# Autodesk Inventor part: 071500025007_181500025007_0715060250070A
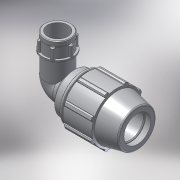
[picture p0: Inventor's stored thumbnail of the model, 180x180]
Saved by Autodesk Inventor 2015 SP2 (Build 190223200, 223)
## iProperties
Created: 2017-02
Part Number: 071500025007_181500025007_0715060250070A
Material: PVC-Piping
Description: PLASSON 90° ELBOW FEMALE ADAPTOR 25-3/4"
Document SubType Name: Modeling
Designer: KIM
Mass: 92.6774 g
Surface Area: 199.44 cm^2
Volume: 66.1981 cm^3
Density: 1.4 g/cm^3
Appearance: Smooth - White
Author: KIM
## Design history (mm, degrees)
derived "07150.ipt"
feature "Solid1::07150.ipt"
tag "TaggingFeature1"
body "Solid1"
other parameters: "d2" = 25, "d4" = 6.75, "d5" = 20.25, "d7" = 54, "d9" = 11.57143, "d11" = 2.7, "d13" = 120 deg, "d14" = 37.5, "d15" = 12 deg, "d16" = 46.98, "d18" = 1.25, "d19" = 35 deg, "d20" = 17.5 deg, "d21" = 50.22, "d23" = 0, "d25" = 360 deg, "d27" = 1.08, "d33" = 0.5, "d42" = 29.97, "d43" = 1.62, "d46" = 0.75, "d51" = 81, "d68" = 2.7, "d72" = 46, "d73" = 31.3521, "d74" = 19, "d75" = 36.05492, "d76" = 24.117, "d77" = 20.9, "d79" = 9.6468, "d80" = 0.72351, "d83" = 0, "d84" = 0, "d91" = 40.5, "d93" = 58, "d94" = 24.117, "d95" = 16.8819, "d96" = 8.1, "d97" = 50 deg, "d98" = 21.7053, "d99" = 0.5, "d100" = 0.5, "d101" = 6.33333, "d102" = 31.3521, "d103" = 16.15, "d104" = 0, "d108" = 360 deg, "d110" = 0.94056, "d_" = 25, "E_" = 54, "A_" = 81, "l_" = 58, "l_2" = 19, "A_1" = 46, "Rp_" = 24.117, "d105" = 4.70281
